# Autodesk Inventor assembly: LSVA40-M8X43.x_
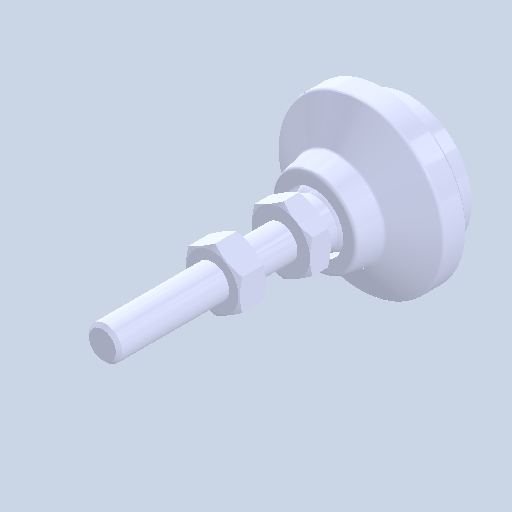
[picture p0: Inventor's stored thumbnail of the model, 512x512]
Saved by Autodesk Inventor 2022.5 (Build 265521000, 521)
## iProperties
Created: 2024-08
Part Number: LSVA40-M8X43.x_
Document SubType Name: Assembly
Designer: ImaoCorp
Author: ImaoCorp
Sending System: SOLIDWORKS 2022-2022290
MC: AMD64
MC_MODEL: Intel64 Family 6 Model 60 Stepping 3, GenuineIntel
OS: Windows_NT
FRU: Parasolid Version 33.1, build 260,  4-25-2022
FORMAT: text
GUISE: transmit
KEY: FILELSVA40-M8X43.x_t
DATE: Fri Aug 23 16:07:56 2024
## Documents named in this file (4)
- X:\14_SW2022-Inv2022\06_2024-10新製品(SME)\ELS_データ\l\lsva40-m8x43\LSVA40-M8X43.x_.iam
- X:\14_SW2022-Inv2022\06_2024-10新製品(SME)\ELS_データ\l\lsva40-m8x43\LSVA40-M8X43_01.ipt
- X:\14_SW2022-Inv2022\06_2024-10新製品(SME)\ELS_データ\l\lsva40-m8x43\LSVA40-M8X43_02.ipt
- X:\14_SW2022-Inv2022\06_2024-10新製品(SME)\ELS_データ\l\lsva40-m8x43\LSVA40-M8X43_03.ipt
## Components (3 placed, 3 different names)
1. LSVA40-M8X43_01
2. LSVA40-M8X43_02
3. LSVA40-M8X43_03
